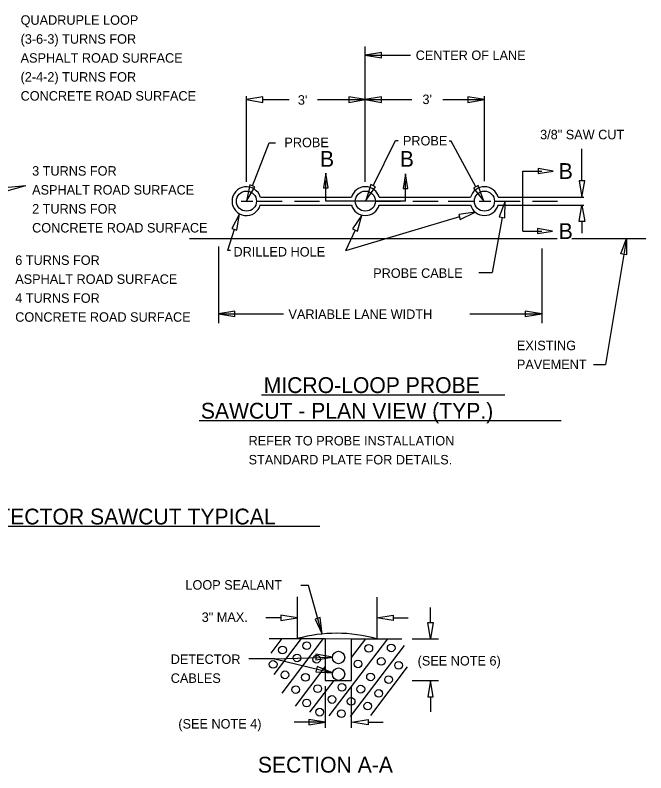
# Model space of a CAD drawing. Extents: x -1550.42 to -1543.2, y 2481.09 to 2491.
# Drawn here: x -1547.504 to -1543.514, y 2486.007 to 2490.803 of the extents above; entities that cross this region are included whole.
import ezdxf

# ---------------------------------------------------------------- set-up
doc = ezdxf.new("R2010")
doc.units = 0
for name, color, linetype in [('DETL-DIMS', 7, 'Continuous'), ('DETL-LINE', 7, 'Continuous'), ('DETL-NOTE', 7, 'Continuous'), ('DETL-PATT', 7, 'Continuous'), ('DETL-TITL', 7, 'Continuous')]:
    doc.layers.add(name, color=color, linetype=linetype)

msp = doc.modelspace()

# ---------------------------------------------------------------- linework, layer by layer
at = {"layer": 'DETL-DIMS'}
for p, q in [((-1545.289, 2489.748), (-1545.289, 2490.605)), ((-1545.289, 2490.549), (-1545.002, 2490.549)), ((-1546.041, 2489.748), (-1546.041, 2490.29)), ((-1545.937, 2490.268), (-1545.7703, 2490.268)), ((-1545.5918, 2490.268), (-1545.289, 2490.268)), ((-1545.289, 2490.268), (-1544.9944, 2490.268)), ((-1544.7986, 2490.268), (-1544.535, 2490.268)), ((-1544.535, 2489.752), (-1544.535, 2490.29)), ((-1545.24, 2489.723), (-1545.098, 2490.009)), ((-1545.098, 2490.009), (-1545.082, 2490.009)), ((-1546.003, 2489.722), (-1545.898, 2489.995)), ((-1545.898, 2489.995), (-1545.857, 2489.995)), ((-1544.745, 2490.006), (-1544.758, 2490.006)), ((-1544.589, 2489.717), (-1544.745, 2490.006)), ((-1543.919, 2489.754), (-1543.919, 2489.957)), ((-1548.177, 2489.653), (-1547.4373, 2489.7251)), ((-1547.697, 2489.651), (-1547.4373, 2489.7251)), ((-1544.693, 2489.526), (-1545.414, 2489.311)), ((-1544.423, 2489.523), (-1544.487, 2489.174)), ((-1543.919, 2489.496), (-1543.919, 2489.422)), ((-1546.118, 2489.447), (-1546.16, 2489.314)), ((-1545.354, 2489.442), (-1545.415, 2489.311)), ((-1543.637, 2489.39), (-1543.77, 2488.592)), ((-1546.218, 2489.338), (-1546.218, 2488.854)), ((-1546.1426, 2489.314), (-1546.16, 2489.314)), ((-1544.173, 2489.325), (-1544.173, 2488.854)), ((-1544.57, 2489.174), (-1544.487, 2489.174)), ((-1546.204, 2488.912), (-1545.807, 2488.912)), ((-1544.627, 2488.912), (-1544.173, 2488.912)), ((-1543.846, 2488.592), (-1543.77, 2488.592)), ((-1545.6494, 2487.192), (-1545.6964, 2487.192)), ((-1545.5621, 2486.8854), (-1545.6494, 2487.192)), ((-1545.72, 2487.12), (-1545.72, 2486.856)), ((-1545.217, 2487.119), (-1545.217, 2486.855)), ((-1544.877, 2486.959), (-1544.877, 2487.054)), ((-1545.824, 2486.988), (-1545.919, 2486.988)), ((-1545.113, 2486.987), (-1545.018, 2486.987)), ((-1544.993, 2486.854), (-1544.826, 2486.854)), ((-1545.861, 2486.728), (-1546.026, 2486.728)), ((-1545.865, 2486.728), (-1545.4974, 2486.7398)), ((-1545.861, 2486.728), (-1545.4968, 2486.639)), ((-1545.542, 2486.555), (-1545.542, 2486.291)), ((-1545.376, 2486.291), (-1545.376, 2486.554)), ((-1544.993, 2486.591), (-1544.826, 2486.591)), ((-1544.877, 2486.488), (-1544.877, 2486.393)), ((-1545.542, 2486.327), (-1545.739, 2486.327)), ((-1545.271, 2486.327), (-1545.176, 2486.327))]:
    msp.add_line(p, q, dxfattribs=at)
for points in [[(-1545.186, 2490.532), (-1545.186, 2490.567), (-1545.29, 2490.549)], [(-1545.937, 2490.251), (-1545.937, 2490.285), (-1546.041, 2490.268)], [(-1545.393, 2490.285), (-1545.393, 2490.251), (-1545.289, 2490.268)], [(-1545.186, 2490.251), (-1545.186, 2490.285), (-1545.29, 2490.268)], [(-1544.64, 2490.285), (-1544.64, 2490.251), (-1544.535, 2490.268)], [(-1544.195, 2489.832), (-1544.195, 2489.801), (-1544.101, 2489.816)], [(-1545.554, 2489.709), (-1545.523, 2489.709), (-1545.539, 2489.803)], [(-1545.05, 2489.705), (-1545.019, 2489.705), (-1545.034, 2489.799)], [(-1545.987, 2489.716), (-1546.02, 2489.729), (-1546.041, 2489.625)], [(-1545.224, 2489.716), (-1545.255, 2489.731), (-1545.286, 2489.63)], [(-1544.574, 2489.725), (-1544.604, 2489.708), (-1544.539, 2489.625)], [(-1543.901, 2489.754), (-1543.936, 2489.754), (-1543.919, 2489.65)], [(-1544.441, 2489.526), (-1544.406, 2489.52), (-1544.405, 2489.625)], [(-1543.901, 2489.496), (-1543.936, 2489.496), (-1543.919, 2489.6)], [(-1546.134, 2489.452), (-1546.101, 2489.442), (-1546.086, 2489.546)], [(-1545.369, 2489.45), (-1545.338, 2489.435), (-1545.31, 2489.537)], [(-1544.698, 2489.542), (-1544.688, 2489.509), (-1544.594, 2489.555)], [(-1544.199, 2489.452), (-1544.199, 2489.421), (-1544.105, 2489.436)], [(-1543.637, 2489.285), (-1543.672, 2489.291), (-1543.637, 2489.39)], [(-1546.114, 2488.895), (-1546.114, 2488.93), (-1546.218, 2488.912)], [(-1544.277, 2488.93), (-1544.277, 2488.895), (-1544.173, 2488.912)], [(-1545.824, 2487.005), (-1545.824, 2486.971), (-1545.72, 2486.988)], [(-1545.5741, 2486.9904), (-1545.6071, 2486.9804), (-1545.5621, 2486.8854)], [(-1545.113, 2487.004), (-1545.113, 2486.97), (-1545.217, 2486.987)], [(-1544.894, 2486.959), (-1544.859, 2486.959), (-1544.877, 2486.855)], [(-1545.6014, 2486.7568), (-1545.6014, 2486.7228), (-1545.4974, 2486.7398)], [(-1545.5938, 2486.68), (-1545.6018, 2486.646), (-1545.4968, 2486.639)], [(-1544.894, 2486.488), (-1544.859, 2486.488), (-1544.877, 2486.592)], [(-1545.646, 2486.344), (-1545.646, 2486.31), (-1545.542, 2486.327)], [(-1545.271, 2486.344), (-1545.271, 2486.31), (-1545.375, 2486.327)]]:
    msp.add_lwpolyline(points, close=True, dxfattribs=at)
for points in [[(-1544.293, 2489.436), (-1544.293, 2489.816)], [(-1544.293, 2489.816), (-1544.173, 2489.816)], [(-1545.539, 2489.625), (-1545.539, 2489.756)], [(-1545.034, 2489.625), (-1545.034, 2489.756)], [(-1544.293, 2489.436), (-1544.173, 2489.436)]]:
    msp.add_lwpolyline(points, dxfattribs=at)
at = {"layer": 'DETL-LINE'}
for p, q in [((-1546.074, 2489.625), (-1546.001, 2489.625)), ((-1545.974, 2489.625), (-1545.815, 2489.625)), ((-1545.953, 2489.65), (-1545.376, 2489.65)), ((-1545.737, 2489.625), (-1545.578, 2489.625)), ((-1545.225, 2489.625), (-1545.066, 2489.625)), ((-1545.201, 2489.65), (-1544.623, 2489.65)), ((-1544.988, 2489.625), (-1544.829, 2489.625)), ((-1544.764, 2489.625), (-1544.605, 2489.625)), ((-1544.568, 2489.625), (-1544.494, 2489.625)), ((-1544.468, 2489.625), (-1544.309, 2489.625)), ((-1544.448, 2489.65), (-1543.906, 2489.65)), ((-1544.231, 2489.625), (-1544.072, 2489.625)), ((-1545.953, 2489.601), (-1545.376, 2489.601)), ((-1545.201, 2489.601), (-1544.623, 2489.601)), ((-1544.448, 2489.601), (-1543.906, 2489.601)), ((-1546.401, 2489.39), (-1544.076, 2489.39)), ((-1543.9822, 2489.39), (-1543.514, 2489.39)), ((-1545.898, 2486.856), (-1545.542, 2486.856)), ((-1545.542, 2486.856), (-1545.376, 2486.855)), ((-1545.542, 2486.856), (-1545.542, 2486.591)), ((-1545.376, 2486.591), (-1545.376, 2486.855)), ((-1545.376, 2486.855), (-1545.058, 2486.855)), ((-1545.546, 2486.66), (-1545.546, 2486.66)), ((-1545.481, 2486.66), (-1545.481, 2486.66)), ((-1545.542, 2486.591), (-1545.376, 2486.591)), ((-1545.449, 2486.595), (-1545.449, 2486.595))]:
    msp.add_line(p, q, dxfattribs=at)
msp.add_lwpolyline([(-1545.034, 2489.625), (-1545.539, 2489.625)], dxfattribs=at)
for centre, radius in [((-1546.0411, 2489.6256), 0.0636), ((-1545.2887, 2489.6256), 0.0636), ((-1544.5354, 2489.6256), 0.0636), ((-1545.4582, 2486.7364), 0.0394), ((-1545.4582, 2486.6314), 0.0394)]:
    msp.add_circle(centre, radius, dxfattribs=at)
for centre, radius, start, end in [((-1546.0411, 2489.6256), 0.091, 15.508, 344.4765), ((-1545.2887, 2489.6256), 0.091, 15.508, 164.492), ((-1544.5354, 2489.6256), 0.091, 15.508, 164.492), ((-1545.2887, 2489.6256), 0.091, 195.5235, 344.4765), ((-1544.5354, 2489.6256), 0.091, 195.5235, 344.4765), ((-1545.4703, 2485.9521), 0.9378, 74.3295, 105.4426)]:
    msp.add_arc(centre, radius, start, end, dxfattribs=at)
at = {"layer": 'DETL-PATT'}
for p, q in [((-1545.884, 2486.764), (-1545.814, 2486.856)), ((-1545.865, 2486.63), (-1545.693, 2486.856)), ((-1545.815, 2486.512), (-1545.553, 2486.856)), ((-1545.518, 2486.367), (-1545.146, 2486.855)), ((-1545.376, 2486.737), (-1545.286, 2486.855)), ((-1545.382, 2486.363), (-1545.04, 2486.812)), ((-1545.731, 2486.429), (-1545.542, 2486.678)), ((-1545.255, 2486.37), (-1545.021, 2486.678)), ((-1545.639, 2486.391), (-1545.487, 2486.591))]:
    msp.add_line(p, q, dxfattribs=at)
for centre in [(-1545.813, 2486.7841), (-1545.6593, 2486.8116), (-1545.2669, 2486.7951), (-1545.1252, 2486.7973), (-1545.7207, 2486.7341), (-1545.5972, 2486.7259), (-1545.8721, 2486.6929), (-1545.3355, 2486.6962), (-1545.1883, 2486.7121), (-1545.0785, 2486.6874), (-1545.7976, 2486.627), (-1545.6676, 2486.6111), (-1545.2559, 2486.6138), (-1545.1417, 2486.5968), (-1545.7289, 2486.5336), (-1545.5907, 2486.5396), (-1545.437, 2486.5479), (-1545.3173, 2486.5363), (-1545.2038, 2486.5094), (-1545.6603, 2486.4484), (-1545.5002, 2486.471), (-1545.3787, 2486.4588), (-1545.578, 2486.3907), (-1545.2734, 2486.4292), (-1545.4401, 2486.3814)]:
    msp.add_circle(centre, 0.0244, dxfattribs=at)
at = {"layer": 'DETL-TITL'}
for p, q in [((-1545.9456, 2488.4002), (-1544.4053, 2488.4002)), ((-1546.3393, 2488.2377), (-1544.049, 2488.2377)), ((-1548.2174, 2487.5684), (-1545.5765, 2487.5684))]:
    msp.add_line(p, q, dxfattribs=at)

# ---------------------------------------------------------------- texts
at = {"layer": 'DETL-NOTE'}
for s, height, p in [('QUADRUPLE LOOP', 0.06, (-1547.47, 2490.742)), ('(3-6-3) TURNS FOR', 0.06, (-1547.47, 2490.622)), ('ASPHALT ROAD SURFACE', 0.06, (-1547.47, 2490.502)), ('CENTER OF LANE', 0.06, (-1544.97, 2490.519)), ('(2-4-2) TURNS FOR', 0.06, (-1547.47, 2490.382)), ('CONCRETE ROAD SURFACE', 0.06, (-1547.47, 2490.262)), ("3'", 0.06, (-1545.7158, 2490.236)), ("3'", 0.06, (-1544.9275, 2490.24)), ('3/8" SAW CUT', 0.06, (-1544.183, 2490.017)), ('PROBE', 0.06, (-1545.801, 2489.967)), ('PROBE', 0.06, (-1545.051, 2489.978)), ('B', 0.1, (-1545.5755, 2489.843)), ('B', 0.1, (-1545.0705, 2489.843)), ('B', 0.1, (-1544.065, 2489.766)), ('3 TURNS FOR', 0.06, (-1547.3971, 2489.787)), ('ASPHALT ROAD SURFACE', 0.06, (-1547.3971, 2489.667)), ('2 TURNS FOR', 0.06, (-1547.3971, 2489.547)), ('CONCRETE ROAD SURFACE', 0.06, (-1547.3971, 2489.427)), ('B', 0.1, (-1544.065, 2489.386)), ('DRILLED HOLE', 0.06, (-1546.123, 2489.275)), ('6 TURNS FOR', 0.06, (-1547.504, 2489.222)), ('PROBE CABLE', 0.06, (-1545.239, 2489.14)), ('ASPHALT ROAD SURFACE', 0.06, (-1547.504, 2489.102)), ('4 TURNS FOR', 0.06, (-1547.504, 2488.982)), ('CONCRETE ROAD SURFACE', 0.06, (-1547.504, 2488.862)), ('VARIABLE LANE WIDTH', 0.06, (-1545.775, 2488.88)), ('EXISTING', 0.06, (-1544.33, 2488.682)), ('PAVEMENT', 0.06, (-1544.33, 2488.562)), ('REFER TO PROBE INSTALLATION', 0.06, (-1546.0275, 2488.079)), ('STANDARD PLATE FOR DETAILS.', 0.06, (-1546.0275, 2487.959)), ('LOOP SEALANT', 0.06, (-1546.427, 2487.1663)), ('3" MAX.', 0.06, (-1546.3241, 2486.9621)), ('DETECTOR', 0.06, (-1546.52, 2486.696)), ('(SEE NOTE 6)', 0.06, (-1544.958, 2486.686)), ('CABLES', 0.06, (-1546.52, 2486.576)), ('(SEE NOTE 4)', 0.06, (-1546.472, 2486.287))]:
    msp.add_text(s, height=height, dxfattribs=at).set_placement(p)
at = {"layer": 'DETL-TITL'}
for s, p in [('MICRO-LOOP PROBE', (-1545.932, 2488.4108)), ('SAWCUT - PLAN VIEW (TYP.)', (-1546.3296, 2488.2488)), ('LOOP DETECTOR SAWCUT TYPICAL', (-1548.212, 2487.579)), ('SECTION A-A', (-1545.9688, 2486.008))]:
    msp.add_text(s, height=0.100002, dxfattribs=at).set_placement(p)

doc.saveas('drawing.dxf')
